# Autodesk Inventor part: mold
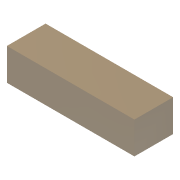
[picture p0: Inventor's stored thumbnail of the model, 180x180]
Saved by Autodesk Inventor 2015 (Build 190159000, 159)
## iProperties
Created: 2016-02
Part Number: mold
Material: Polycarbonate, Smoke
Document SubType Name: Modeling
Designer: Hafliði
Density: 1.2 g/cm^3
Appearance: Polycarbonate - Smoked
Author: Hafliði
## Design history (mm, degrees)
sketch "Sketch1"
  geometry: L1 (-280, 70)-(280, 70); L2 (280, 70)-(280, -70); L3 (280, -70)-(-280, -70); L4 (-280, -70)-(-280, 70); L5 (-280, 70)-(280, -70); L6 (280, 70)-(-280, -70); 1 further point
  constraints: 12 end point, 2 midpoint, 2 parallel, 1 horizontal, 1 perpendicular
  dimensions: "d0" = 560 distance of L2.end L3.end; "d1" = 140 distance of L1.end L2.end
extrude "Extrusion1" new body sketch "Sketch1" distance "d2" = 170; taper "d3" = 0 deg
body "Solid1"
